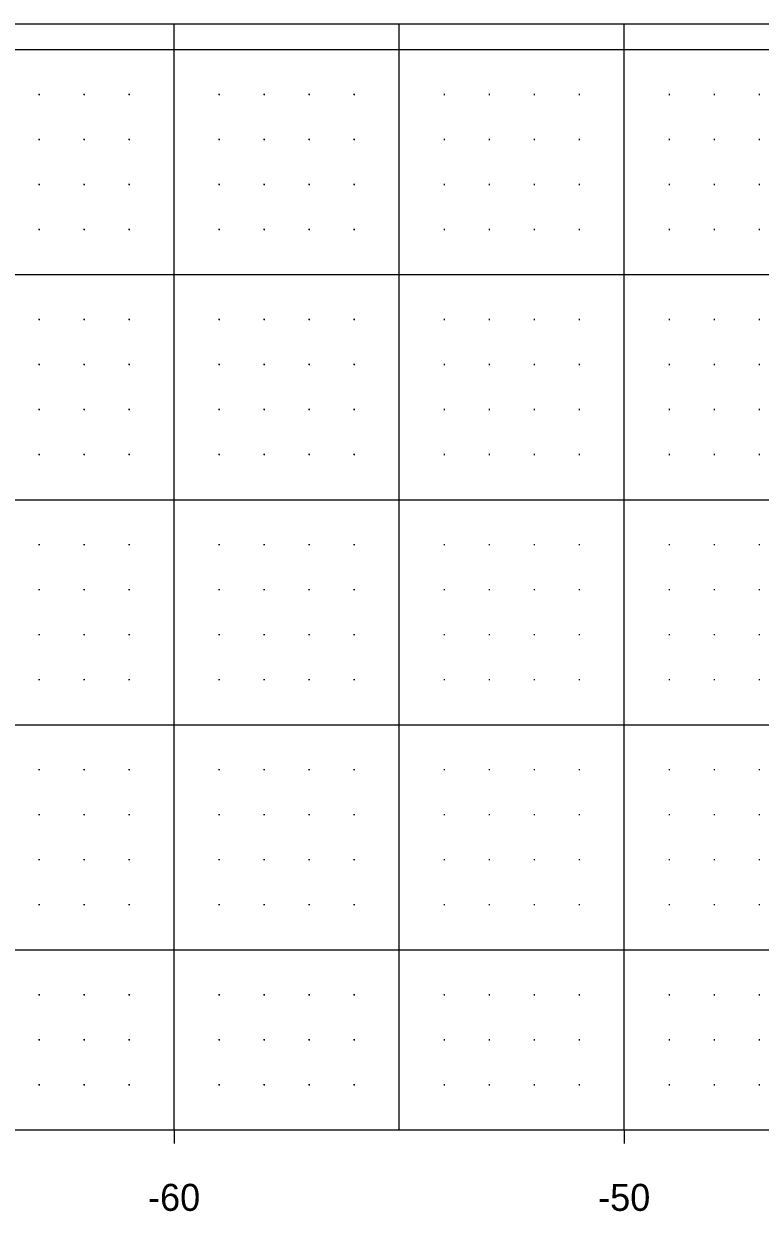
# Model space of a CAD drawing. Extents: x -80 to 80, y 222 to 253.
# Drawn here: x -63.34 to -46.98, y 224.19 to 250.57 of the extents above; entities that cross this region are included whole.
import ezdxf

# ---------------------------------------------------------------- set-up
doc = ezdxf.new("R2010")
doc.units = 0
for name, color, linetype in [('DSN_DRFT_XS Border Grid', 7, 'Continuous'), ('DSN_DRFT_XS Grid Annotations', 7, 'Continuous'), ('DSN_DRFT_XS Grid Major', 7, 'Continuous'), ('DSN_DRFT_XS Grid Minor', 7, 'Continuous')]:
    doc.layers.add(name, color=color, linetype=linetype)

msp = doc.modelspace()

# ---------------------------------------------------------------- linework, layer by layer
at = {"layer": 'DSN_DRFT_XS Border Grid'}
for p, q in [((-77.5, 250.573), (77.5, 250.573)), ((-77.5, 226), (77.5, 226))]:
    msp.add_line(p, q, dxfattribs=at)
at = {"layer": 'DSN_DRFT_XS Grid Major'}
for p, q in [((-60, 226), (-60, 250.573)), ((-55, 226), (-55, 250.573)), ((-50, 226), (-50, 250.573)), ((-77.5, 250), (77.5, 250)), ((-77.5, 245), (77.5, 245)), ((-77.5, 240), (77.5, 240)), ((-77.5, 235), (77.5, 235)), ((-77.5, 230), (77.5, 230)), ((-60, 226), (-60, 225.7)), ((-50, 226), (-50, 225.7))]:
    msp.add_line(p, q, dxfattribs=at)
at = {"layer": 'DSN_DRFT_XS Grid Minor'}
for p, q in [((-62.988, 249), (-63.012, 249)), ((-63, 249.012), (-63, 248.988)), ((-61.988, 249), (-62.012, 249)), ((-62, 249.012), (-62, 248.988)), ((-60.988, 249), (-61.012, 249)), ((-61, 249.012), (-61, 248.988)), ((-58.988, 249), (-59.012, 249)), ((-59, 249.012), (-59, 248.988)), ((-57.988, 249), (-58.012, 249)), ((-58, 249.012), (-58, 248.988)), ((-56.988, 249), (-57.012, 249)), ((-57, 249.012), (-57, 248.988)), ((-55.988, 249), (-56.012, 249)), ((-56, 249.012), (-56, 248.988)), ((-53.988, 249), (-54.012, 249)), ((-54, 249.012), (-54, 248.988)), ((-52.988, 249), (-53.012, 249)), ((-53, 249.012), (-53, 248.988)), ((-51.988, 249), (-52.012, 249)), ((-52, 249.012), (-52, 248.988)), ((-50.988, 249), (-51.012, 249)), ((-51, 249.012), (-51, 248.988)), ((-48.988, 249), (-49.012, 249)), ((-49, 249.012), (-49, 248.988)), ((-47.988, 249), (-48.012, 249)), ((-48, 249.012), (-48, 248.988)), ((-46.988, 249), (-47.012, 249)), ((-47, 249.012), (-47, 248.988)), ((-62.988, 248), (-63.012, 248)), ((-63, 248.012), (-63, 247.988)), ((-61.988, 248), (-62.012, 248)), ((-62, 248.012), (-62, 247.988)), ((-60.988, 248), (-61.012, 248)), ((-61, 248.012), (-61, 247.988)), ((-58.988, 248), (-59.012, 248)), ((-59, 248.012), (-59, 247.988)), ((-57.988, 248), (-58.012, 248)), ((-58, 248.012), (-58, 247.988)), ((-56.988, 248), (-57.012, 248)), ((-57, 248.012), (-57, 247.988)), ((-55.988, 248), (-56.012, 248)), ((-56, 248.012), (-56, 247.988)), ((-53.988, 248), (-54.012, 248)), ((-54, 248.012), (-54, 247.988)), ((-52.988, 248), (-53.012, 248)), ((-53, 248.012), (-53, 247.988)), ((-51.988, 248), (-52.012, 248)), ((-52, 248.012), (-52, 247.988)), ((-50.988, 248), (-51.012, 248)), ((-51, 248.012), (-51, 247.988)), ((-48.988, 248), (-49.012, 248)), ((-49, 248.012), (-49, 247.988)), ((-47.988, 248), (-48.012, 248)), ((-48, 248.012), (-48, 247.988)), ((-46.988, 248), (-47.012, 248)), ((-47, 248.012), (-47, 247.988)), ((-62.988, 247), (-63.012, 247)), ((-63, 247.012), (-63, 246.988)), ((-61.988, 247), (-62.012, 247)), ((-62, 247.012), (-62, 246.988)), ((-60.988, 247), (-61.012, 247)), ((-61, 247.012), (-61, 246.988)), ((-58.988, 247), (-59.012, 247)), ((-59, 247.012), (-59, 246.988)), ((-57.988, 247), (-58.012, 247)), ((-58, 247.012), (-58, 246.988)), ((-56.988, 247), (-57.012, 247)), ((-57, 247.012), (-57, 246.988)), ((-55.988, 247), (-56.012, 247)), ((-56, 247.012), (-56, 246.988)), ((-53.988, 247), (-54.012, 247)), ((-54, 247.012), (-54, 246.988)), ((-52.988, 247), (-53.012, 247)), ((-53, 247.012), (-53, 246.988)), ((-51.988, 247), (-52.012, 247)), ((-52, 247.012), (-52, 246.988)), ((-50.988, 247), (-51.012, 247)), ((-51, 247.012), (-51, 246.988)), ((-48.988, 247), (-49.012, 247)), ((-49, 247.012), (-49, 246.988)), ((-47.988, 247), (-48.012, 247)), ((-48, 247.012), (-48, 246.988)), ((-46.988, 247), (-47.012, 247)), ((-47, 247.012), (-47, 246.988)), ((-62.988, 246), (-63.012, 246)), ((-63, 246.012), (-63, 245.988)), ((-61.988, 246), (-62.012, 246)), ((-62, 246.012), (-62, 245.988)), ((-60.988, 246), (-61.012, 246)), ((-61, 246.012), (-61, 245.988)), ((-58.988, 246), (-59.012, 246)), ((-59, 246.012), (-59, 245.988)), ((-57.988, 246), (-58.012, 246)), ((-58, 246.012), (-58, 245.988)), ((-56.988, 246), (-57.012, 246)), ((-57, 246.012), (-57, 245.988)), ((-55.988, 246), (-56.012, 246)), ((-56, 246.012), (-56, 245.988)), ((-53.988, 246), (-54.012, 246)), ((-54, 246.012), (-54, 245.988)), ((-52.988, 246), (-53.012, 246)), ((-53, 246.012), (-53, 245.988)), ((-51.988, 246), (-52.012, 246)), ((-52, 246.012), (-52, 245.988)), ((-50.988, 246), (-51.012, 246)), ((-51, 246.012), (-51, 245.988)), ((-48.988, 246), (-49.012, 246)), ((-49, 246.012), (-49, 245.988)), ((-47.988, 246), (-48.012, 246)), ((-48, 246.012), (-48, 245.988)), ((-46.988, 246), (-47.012, 246)), ((-47, 246.012), (-47, 245.988)), ((-62.988, 244), (-63.012, 244)), ((-63, 244.012), (-63, 243.988)), ((-61.988, 244), (-62.012, 244)), ((-62, 244.012), (-62, 243.988)), ((-60.988, 244), (-61.012, 244)), ((-61, 244.012), (-61, 243.988)), ((-58.988, 244), (-59.012, 244)), ((-59, 244.012), (-59, 243.988)), ((-57.988, 244), (-58.012, 244)), ((-58, 244.012), (-58, 243.988)), ((-56.988, 244), (-57.012, 244)), ((-57, 244.012), (-57, 243.988)), ((-55.988, 244), (-56.012, 244)), ((-56, 244.012), (-56, 243.988)), ((-53.988, 244), (-54.012, 244)), ((-54, 244.012), (-54, 243.988)), ((-52.988, 244), (-53.012, 244)), ((-53, 244.012), (-53, 243.988)), ((-51.988, 244), (-52.012, 244)), ((-52, 244.012), (-52, 243.988)), ((-50.988, 244), (-51.012, 244)), ((-51, 244.012), (-51, 243.988)), ((-48.988, 244), (-49.012, 244)), ((-49, 244.012), (-49, 243.988)), ((-47.988, 244), (-48.012, 244)), ((-48, 244.012), (-48, 243.988)), ((-46.988, 244), (-47.012, 244)), ((-47, 244.012), (-47, 243.988)), ((-62.988, 243), (-63.012, 243)), ((-63, 243.012), (-63, 242.988)), ((-61.988, 243), (-62.012, 243)), ((-62, 243.012), (-62, 242.988)), ((-60.988, 243), (-61.012, 243)), ((-61, 243.012), (-61, 242.988)), ((-58.988, 243), (-59.012, 243)), ((-59, 243.012), (-59, 242.988)), ((-57.988, 243), (-58.012, 243)), ((-58, 243.012), (-58, 242.988)), ((-56.988, 243), (-57.012, 243)), ((-57, 243.012), (-57, 242.988)), ((-55.988, 243), (-56.012, 243)), ((-56, 243.012), (-56, 242.988)), ((-53.988, 243), (-54.012, 243)), ((-54, 243.012), (-54, 242.988)), ((-52.988, 243), (-53.012, 243)), ((-53, 243.012), (-53, 242.988)), ((-51.988, 243), (-52.012, 243)), ((-52, 243.012), (-52, 242.988)), ((-50.988, 243), (-51.012, 243)), ((-51, 243.012), (-51, 242.988)), ((-48.988, 243), (-49.012, 243)), ((-49, 243.012), (-49, 242.988)), ((-47.988, 243), (-48.012, 243)), ((-48, 243.012), (-48, 242.988)), ((-46.988, 243), (-47.012, 243)), ((-47, 243.012), (-47, 242.988)), ((-62.988, 242), (-63.012, 242)), ((-63, 242.012), (-63, 241.988)), ((-61.988, 242), (-62.012, 242)), ((-62, 242.012), (-62, 241.988)), ((-60.988, 242), (-61.012, 242)), ((-61, 242.012), (-61, 241.988)), ((-58.988, 242), (-59.012, 242)), ((-59, 242.012), (-59, 241.988)), ((-57.988, 242), (-58.012, 242)), ((-58, 242.012), (-58, 241.988)), ((-56.988, 242), (-57.012, 242)), ((-57, 242.012), (-57, 241.988)), ((-55.988, 242), (-56.012, 242)), ((-56, 242.012), (-56, 241.988)), ((-53.988, 242), (-54.012, 242)), ((-54, 242.012), (-54, 241.988)), ((-52.988, 242), (-53.012, 242)), ((-53, 242.012), (-53, 241.988)), ((-51.988, 242), (-52.012, 242)), ((-52, 242.012), (-52, 241.988)), ((-50.988, 242), (-51.012, 242)), ((-51, 242.012), (-51, 241.988)), ((-48.988, 242), (-49.012, 242)), ((-49, 242.012), (-49, 241.988)), ((-47.988, 242), (-48.012, 242)), ((-48, 242.012), (-48, 241.988)), ((-46.988, 242), (-47.012, 242)), ((-47, 242.012), (-47, 241.988)), ((-62.988, 241), (-63.012, 241)), ((-63, 241.012), (-63, 240.988)), ((-61.988, 241), (-62.012, 241)), ((-62, 241.012), (-62, 240.988)), ((-60.988, 241), (-61.012, 241)), ((-61, 241.012), (-61, 240.988)), ((-58.988, 241), (-59.012, 241)), ((-59, 241.012), (-59, 240.988)), ((-57.988, 241), (-58.012, 241)), ((-58, 241.012), (-58, 240.988)), ((-56.988, 241), (-57.012, 241)), ((-57, 241.012), (-57, 240.988)), ((-55.988, 241), (-56.012, 241)), ((-56, 241.012), (-56, 240.988)), ((-53.988, 241), (-54.012, 241)), ((-54, 241.012), (-54, 240.988)), ((-52.988, 241), (-53.012, 241)), ((-53, 241.012), (-53, 240.988)), ((-51.988, 241), (-52.012, 241)), ((-52, 241.012), (-52, 240.988)), ((-50.988, 241), (-51.012, 241)), ((-51, 241.012), (-51, 240.988)), ((-48.988, 241), (-49.012, 241)), ((-49, 241.012), (-49, 240.988)), ((-47.988, 241), (-48.012, 241)), ((-48, 241.012), (-48, 240.988)), ((-46.988, 241), (-47.012, 241)), ((-47, 241.012), (-47, 240.988)), ((-62.988, 239), (-63.012, 239)), ((-63, 239.012), (-63, 238.988)), ((-61.988, 239), (-62.012, 239)), ((-62, 239.012), (-62, 238.988)), ((-60.988, 239), (-61.012, 239)), ((-61, 239.012), (-61, 238.988)), ((-58.988, 239), (-59.012, 239)), ((-59, 239.012), (-59, 238.988)), ((-57.988, 239), (-58.012, 239)), ((-58, 239.012), (-58, 238.988)), ((-56.988, 239), (-57.012, 239)), ((-57, 239.012), (-57, 238.988)), ((-55.988, 239), (-56.012, 239)), ((-56, 239.012), (-56, 238.988)), ((-53.988, 239), (-54.012, 239)), ((-54, 239.012), (-54, 238.988)), ((-52.988, 239), (-53.012, 239)), ((-53, 239.012), (-53, 238.988)), ((-51.988, 239), (-52.012, 239)), ((-52, 239.012), (-52, 238.988)), ((-50.988, 239), (-51.012, 239)), ((-51, 239.012), (-51, 238.988)), ((-48.988, 239), (-49.012, 239)), ((-49, 239.012), (-49, 238.988)), ((-47.988, 239), (-48.012, 239)), ((-48, 239.012), (-48, 238.988)), ((-46.988, 239), (-47.012, 239)), ((-47, 239.012), (-47, 238.988)), ((-62.988, 238), (-63.012, 238)), ((-63, 238.012), (-63, 237.988)), ((-61.988, 238), (-62.012, 238)), ((-62, 238.012), (-62, 237.988)), ((-60.988, 238), (-61.012, 238)), ((-61, 238.012), (-61, 237.988)), ((-58.988, 238), (-59.012, 238)), ((-59, 238.012), (-59, 237.988)), ((-57.988, 238), (-58.012, 238)), ((-58, 238.012), (-58, 237.988)), ((-56.988, 238), (-57.012, 238)), ((-57, 238.012), (-57, 237.988)), ((-55.988, 238), (-56.012, 238)), ((-56, 238.012), (-56, 237.988)), ((-53.988, 238), (-54.012, 238)), ((-54, 238.012), (-54, 237.988)), ((-52.988, 238), (-53.012, 238)), ((-53, 238.012), (-53, 237.988)), ((-51.988, 238), (-52.012, 238)), ((-52, 238.012), (-52, 237.988)), ((-50.988, 238), (-51.012, 238)), ((-51, 238.012), (-51, 237.988)), ((-48.988, 238), (-49.012, 238)), ((-49, 238.012), (-49, 237.988)), ((-47.988, 238), (-48.012, 238)), ((-48, 238.012), (-48, 237.988)), ((-46.988, 238), (-47.012, 238)), ((-47, 238.012), (-47, 237.988)), ((-62.988, 237), (-63.012, 237)), ((-63, 237.012), (-63, 236.988)), ((-61.988, 237), (-62.012, 237)), ((-62, 237.012), (-62, 236.988)), ((-60.988, 237), (-61.012, 237)), ((-61, 237.012), (-61, 236.988)), ((-58.988, 237), (-59.012, 237)), ((-59, 237.012), (-59, 236.988)), ((-57.988, 237), (-58.012, 237)), ((-58, 237.012), (-58, 236.988)), ((-56.988, 237), (-57.012, 237)), ((-57, 237.012), (-57, 236.988)), ((-55.988, 237), (-56.012, 237)), ((-56, 237.012), (-56, 236.988)), ((-53.988, 237), (-54.012, 237)), ((-54, 237.012), (-54, 236.988)), ((-52.988, 237), (-53.012, 237)), ((-53, 237.012), (-53, 236.988)), ((-51.988, 237), (-52.012, 237)), ((-52, 237.012), (-52, 236.988)), ((-50.988, 237), (-51.012, 237)), ((-51, 237.012), (-51, 236.988)), ((-48.988, 237), (-49.012, 237)), ((-49, 237.012), (-49, 236.988)), ((-47.988, 237), (-48.012, 237)), ((-48, 237.012), (-48, 236.988)), ((-46.988, 237), (-47.012, 237)), ((-47, 237.012), (-47, 236.988)), ((-62.988, 236), (-63.012, 236)), ((-63, 236.012), (-63, 235.988)), ((-61.988, 236), (-62.012, 236)), ((-62, 236.012), (-62, 235.988)), ((-60.988, 236), (-61.012, 236)), ((-61, 236.012), (-61, 235.988)), ((-58.988, 236), (-59.012, 236)), ((-59, 236.012), (-59, 235.988)), ((-57.988, 236), (-58.012, 236)), ((-58, 236.012), (-58, 235.988)), ((-56.988, 236), (-57.012, 236)), ((-57, 236.012), (-57, 235.988)), ((-55.988, 236), (-56.012, 236)), ((-56, 236.012), (-56, 235.988)), ((-53.988, 236), (-54.012, 236)), ((-54, 236.012), (-54, 235.988)), ((-52.988, 236), (-53.012, 236)), ((-53, 236.012), (-53, 235.988)), ((-51.988, 236), (-52.012, 236)), ((-52, 236.012), (-52, 235.988)), ((-50.988, 236), (-51.012, 236)), ((-51, 236.012), (-51, 235.988)), ((-48.988, 236), (-49.012, 236)), ((-49, 236.012), (-49, 235.988)), ((-47.988, 236), (-48.012, 236)), ((-48, 236.012), (-48, 235.988)), ((-46.988, 236), (-47.012, 236)), ((-47, 236.012), (-47, 235.988)), ((-63, 234.012), (-63, 233.988)), ((-62, 234.012), (-62, 233.988)), ((-61, 234.012), (-61, 233.988)), ((-59, 234.012), (-59, 233.988)), ((-58, 234.012), (-58, 233.988)), ((-57, 234.012), (-57, 233.988)), ((-56, 234.012), (-56, 233.988)), ((-54, 234.012), (-54, 233.988)), ((-53, 234.012), (-53, 233.988)), ((-52, 234.012), (-52, 233.988)), ((-51, 234.012), (-51, 233.988)), ((-49, 234.012), (-49, 233.988)), ((-48, 234.012), (-48, 233.988)), ((-47, 234.012), (-47, 233.988)), ((-62.988, 234), (-63.012, 234)), ((-61.988, 234), (-62.012, 234)), ((-60.988, 234), (-61.012, 234)), ((-58.988, 234), (-59.012, 234)), ((-57.988, 234), (-58.012, 234)), ((-56.988, 234), (-57.012, 234)), ((-55.988, 234), (-56.012, 234)), ((-53.988, 234), (-54.012, 234)), ((-52.988, 234), (-53.012, 234)), ((-51.988, 234), (-52.012, 234)), ((-50.988, 234), (-51.012, 234)), ((-48.988, 234), (-49.012, 234)), ((-47.988, 234), (-48.012, 234)), ((-46.988, 234), (-47.012, 234)), ((-62.988, 233), (-63.012, 233)), ((-63, 233.012), (-63, 232.988)), ((-61.988, 233), (-62.012, 233)), ((-62, 233.012), (-62, 232.988)), ((-60.988, 233), (-61.012, 233)), ((-61, 233.012), (-61, 232.988)), ((-58.988, 233), (-59.012, 233)), ((-59, 233.012), (-59, 232.988)), ((-57.988, 233), (-58.012, 233)), ((-58, 233.012), (-58, 232.988)), ((-56.988, 233), (-57.012, 233)), ((-57, 233.012), (-57, 232.988)), ((-55.988, 233), (-56.012, 233)), ((-56, 233.012), (-56, 232.988)), ((-53.988, 233), (-54.012, 233)), ((-54, 233.012), (-54, 232.988)), ((-52.988, 233), (-53.012, 233)), ((-53, 233.012), (-53, 232.988)), ((-51.988, 233), (-52.012, 233)), ((-52, 233.012), (-52, 232.988)), ((-50.988, 233), (-51.012, 233)), ((-51, 233.012), (-51, 232.988)), ((-48.988, 233), (-49.012, 233)), ((-49, 233.012), (-49, 232.988)), ((-47.988, 233), (-48.012, 233)), ((-48, 233.012), (-48, 232.988)), ((-46.988, 233), (-47.012, 233)), ((-47, 233.012), (-47, 232.988)), ((-62.988, 232), (-63.012, 232)), ((-63, 232.012), (-63, 231.988)), ((-61.988, 232), (-62.012, 232)), ((-62, 232.012), (-62, 231.988)), ((-60.988, 232), (-61.012, 232)), ((-61, 232.012), (-61, 231.988)), ((-58.988, 232), (-59.012, 232)), ((-59, 232.012), (-59, 231.988)), ((-57.988, 232), (-58.012, 232)), ((-58, 232.012), (-58, 231.988)), ((-56.988, 232), (-57.012, 232)), ((-57, 232.012), (-57, 231.988)), ((-55.988, 232), (-56.012, 232)), ((-56, 232.012), (-56, 231.988)), ((-53.988, 232), (-54.012, 232)), ((-54, 232.012), (-54, 231.988)), ((-52.988, 232), (-53.012, 232)), ((-53, 232.012), (-53, 231.988)), ((-51.988, 232), (-52.012, 232)), ((-52, 232.012), (-52, 231.988)), ((-50.988, 232), (-51.012, 232)), ((-51, 232.012), (-51, 231.988)), ((-48.988, 232), (-49.012, 232)), ((-49, 232.012), (-49, 231.988)), ((-47.988, 232), (-48.012, 232)), ((-48, 232.012), (-48, 231.988)), ((-46.988, 232), (-47.012, 232)), ((-47, 232.012), (-47, 231.988)), ((-62.988, 231), (-63.012, 231)), ((-63, 231.012), (-63, 230.988)), ((-61.988, 231), (-62.012, 231)), ((-62, 231.012), (-62, 230.988)), ((-60.988, 231), (-61.012, 231)), ((-61, 231.012), (-61, 230.988)), ((-58.988, 231), (-59.012, 231)), ((-59, 231.012), (-59, 230.988)), ((-57.988, 231), (-58.012, 231)), ((-58, 231.012), (-58, 230.988)), ((-56.988, 231), (-57.012, 231)), ((-57, 231.012), (-57, 230.988)), ((-55.988, 231), (-56.012, 231)), ((-56, 231.012), (-56, 230.988)), ((-53.988, 231), (-54.012, 231)), ((-54, 231.012), (-54, 230.988)), ((-52.988, 231), (-53.012, 231)), ((-53, 231.012), (-53, 230.988)), ((-51.988, 231), (-52.012, 231)), ((-52, 231.012), (-52, 230.988)), ((-50.988, 231), (-51.012, 231)), ((-51, 231.012), (-51, 230.988)), ((-48.988, 231), (-49.012, 231)), ((-49, 231.012), (-49, 230.988)), ((-47.988, 231), (-48.012, 231)), ((-48, 231.012), (-48, 230.988)), ((-46.988, 231), (-47.012, 231)), ((-47, 231.012), (-47, 230.988)), ((-62.988, 229), (-63.012, 229)), ((-63, 229.012), (-63, 228.988)), ((-61.988, 229), (-62.012, 229)), ((-62, 229.012), (-62, 228.988)), ((-60.988, 229), (-61.012, 229)), ((-61, 229.012), (-61, 228.988)), ((-58.988, 229), (-59.012, 229)), ((-59, 229.012), (-59, 228.988)), ((-57.988, 229), (-58.012, 229)), ((-58, 229.012), (-58, 228.988)), ((-56.988, 229), (-57.012, 229)), ((-57, 229.012), (-57, 228.988)), ((-55.988, 229), (-56.012, 229)), ((-56, 229.012), (-56, 228.988)), ((-53.988, 229), (-54.012, 229)), ((-54, 229.012), (-54, 228.988)), ((-52.988, 229), (-53.012, 229)), ((-53, 229.012), (-53, 228.988)), ((-51.988, 229), (-52.012, 229)), ((-52, 229.012), (-52, 228.988)), ((-50.988, 229), (-51.012, 229)), ((-51, 229.012), (-51, 228.988)), ((-48.988, 229), (-49.012, 229)), ((-49, 229.012), (-49, 228.988)), ((-47.988, 229), (-48.012, 229)), ((-48, 229.012), (-48, 228.988)), ((-46.988, 229), (-47.012, 229)), ((-47, 229.012), (-47, 228.988)), ((-62.988, 228), (-63.012, 228)), ((-63, 228.012), (-63, 227.988)), ((-61.988, 228), (-62.012, 228)), ((-62, 228.012), (-62, 227.988)), ((-60.988, 228), (-61.012, 228)), ((-61, 228.012), (-61, 227.988)), ((-58.988, 228), (-59.012, 228)), ((-59, 228.012), (-59, 227.988)), ((-57.988, 228), (-58.012, 228)), ((-58, 228.012), (-58, 227.988)), ((-56.988, 228), (-57.012, 228)), ((-57, 228.012), (-57, 227.988)), ((-55.988, 228), (-56.012, 228)), ((-56, 228.012), (-56, 227.988)), ((-53.988, 228), (-54.012, 228)), ((-54, 228.012), (-54, 227.988)), ((-52.988, 228), (-53.012, 228)), ((-53, 228.012), (-53, 227.988)), ((-51.988, 228), (-52.012, 228)), ((-52, 228.012), (-52, 227.988)), ((-50.988, 228), (-51.012, 228)), ((-51, 228.012), (-51, 227.988)), ((-48.988, 228), (-49.012, 228)), ((-49, 228.012), (-49, 227.988)), ((-47.988, 228), (-48.012, 228)), ((-48, 228.012), (-48, 227.988)), ((-46.988, 228), (-47.012, 228)), ((-47, 228.012), (-47, 227.988)), ((-62.988, 227), (-63.012, 227)), ((-63, 227.012), (-63, 226.988)), ((-61.988, 227), (-62.012, 227)), ((-62, 227.012), (-62, 226.988)), ((-60.988, 227), (-61.012, 227)), ((-61, 227.012), (-61, 226.988)), ((-58.988, 227), (-59.012, 227)), ((-59, 227.012), (-59, 226.988)), ((-57.988, 227), (-58.012, 227)), ((-58, 227.012), (-58, 226.988)), ((-56.988, 227), (-57.012, 227)), ((-57, 227.012), (-57, 226.988)), ((-55.988, 227), (-56.012, 227)), ((-56, 227.012), (-56, 226.988)), ((-53.988, 227), (-54.012, 227)), ((-54, 227.012), (-54, 226.988)), ((-52.988, 227), (-53.012, 227)), ((-53, 227.012), (-53, 226.988)), ((-51.988, 227), (-52.012, 227)), ((-52, 227.012), (-52, 226.988)), ((-50.988, 227), (-51.012, 227)), ((-51, 227.012), (-51, 226.988)), ((-48.988, 227), (-49.012, 227)), ((-49, 227.012), (-49, 226.988)), ((-47.988, 227), (-48.012, 227)), ((-48, 227.012), (-48, 226.988)), ((-46.988, 227), (-47.012, 227)), ((-47, 227.012), (-47, 226.988))]:
    msp.add_line(p, q, dxfattribs=at)

# ---------------------------------------------------------------- texts
at = {"layer": 'DSN_DRFT_XS Grid Annotations'}
for s, p in [('-60', (-60.581, 224.2)), ('-50', (-50.581, 224.2))]:
    msp.add_text(s, height=0.6, dxfattribs=at).set_placement(p)

doc.saveas('drawing.dxf')
